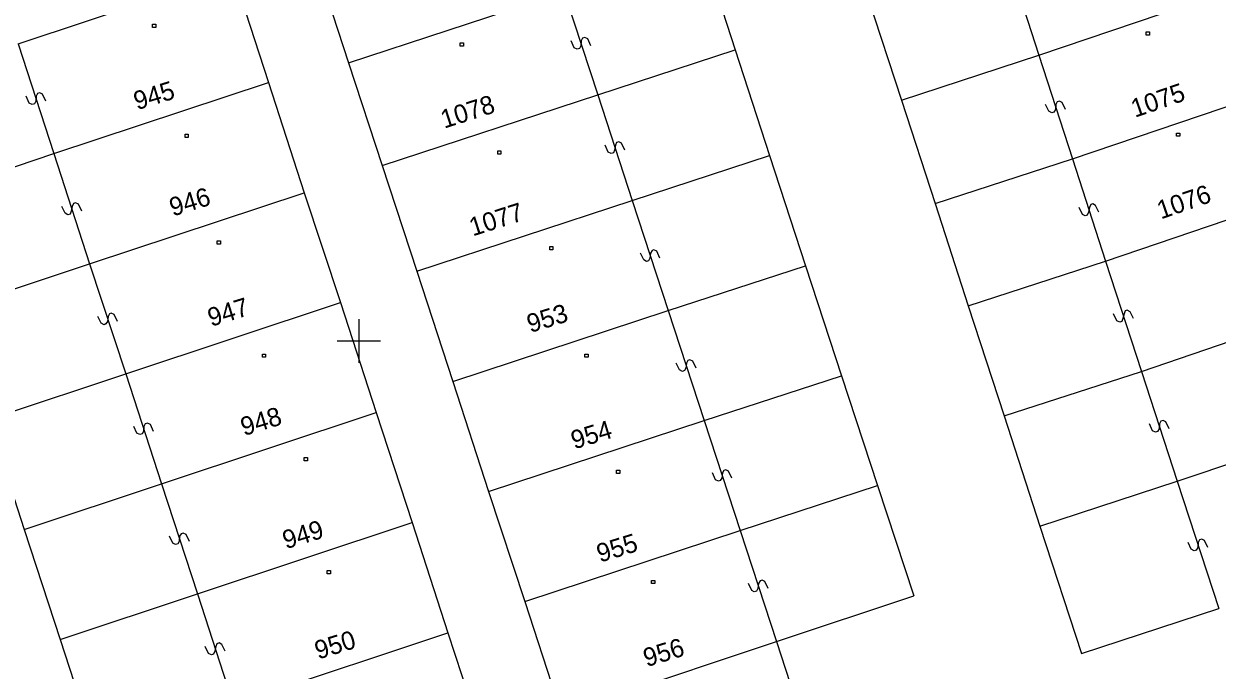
# Model space of a CAD drawing. Extents: x -493352 to -492964, y -1127001 to -1126712.
# Drawn here: x -493269.27 to -493236.25, y -1126749.1 to -1126731.23 of the extents above; entities that cross this region are included whole.
import ezdxf

# ---------------------------------------------------------------- set-up
doc = ezdxf.new("R2010")
doc.units = 0
doc.layers.add('katastrální mapa', color=7, linetype='Continuous')
doc.layers.add('síť', color=7, linetype='Continuous')

msp = doc.modelspace()

# ---------------------------------------------------------------- linework, layer by layer
at = {"layer": 'katastrální mapa'}
for p, q in [((-493250.52, -1126729.1), (-493249.59, -1126731.95)), ((-493242.11, -1126729.25), (-493241.19, -1126732.1)), ((-493261.22, -1126729.46), (-493260.29, -1126732.31)), ((-493269.43, -1126731.78), (-493263.49, -1126729.81)), ((-493263.49, -1126729.81), (-493262.5, -1126732.85)), ((-493241.19, -1126732.1), (-493235.35, -1126730.12)), ((-493260.29, -1126732.31), (-493254.32, -1126730.35)), ((-493254.32, -1126730.35), (-493253.39, -1126733.19)), ((-493245.92, -1126730.49), (-493244.99, -1126733.34)), ((-493265.71, -1126731.24), (-493265.62, -1126731.24)), ((-493265.71, -1126731.33), (-493265.71, -1126731.24)), ((-493265.62, -1126731.33), (-493265.71, -1126731.33)), ((-493265.62, -1126731.24), (-493265.62, -1126731.33)), ((-493238.22, -1126731.45), (-493238.13, -1126731.45)), ((-493238.22, -1126731.54), (-493238.22, -1126731.45)), ((-493238.13, -1126731.54), (-493238.22, -1126731.54)), ((-493238.13, -1126731.45), (-493238.13, -1126731.54)), ((-493269.43, -1126731.78), (-493268.44, -1126734.82)), ((-493257.2, -1126731.76), (-493257.11, -1126731.76)), ((-493257.2, -1126731.85), (-493257.2, -1126731.76)), ((-493257.11, -1126731.85), (-493257.2, -1126731.85)), ((-493257.11, -1126731.76), (-493257.11, -1126731.85)), ((-493254.04, -1126731.89), (-493254.13, -1126731.7)), ((-493253.96, -1126731.93), (-493254.04, -1126731.89)), ((-493253.86, -1126731.84), (-493253.9, -1126731.91)), ((-493253.85, -1126731.7), (-493253.86, -1126731.84)), ((-493253.81, -1126731.63), (-493253.85, -1126731.7)), ((-493253.75, -1126731.61), (-493253.81, -1126731.63)), ((-493253.67, -1126731.65), (-493253.75, -1126731.61)), ((-493253.58, -1126731.84), (-493253.67, -1126731.65)), ((-493253.9, -1126731.91), (-493253.96, -1126731.93)), ((-493253.39, -1126733.19), (-493249.59, -1126731.95)), ((-493249.59, -1126731.95), (-493248.64, -1126734.87)), ((-493244.99, -1126733.34), (-493241.19, -1126732.1)), ((-493241.19, -1126732.1), (-493240.26, -1126734.96)), ((-493260.29, -1126732.31), (-493259.36, -1126735.15)), ((-493268.44, -1126734.82), (-493262.5, -1126732.85)), ((-493262.5, -1126732.85), (-493261.51, -1126735.9)), ((-493268.89, -1126733.16), (-493268.93, -1126733.23)), ((-493268.83, -1126733.14), (-493268.89, -1126733.16)), ((-493268.75, -1126733.18), (-493268.83, -1126733.14)), ((-493268.66, -1126733.37), (-493268.75, -1126733.18)), ((-493259.36, -1126735.15), (-493253.39, -1126733.19)), ((-493253.39, -1126733.19), (-493252.44, -1126736.12)), ((-493240.26, -1126734.96), (-493234.43, -1126732.99)), ((-493269.12, -1126733.42), (-493269.21, -1126733.23)), ((-493269.04, -1126733.46), (-493269.12, -1126733.42)), ((-493268.98, -1126733.44), (-493269.04, -1126733.46)), ((-493268.94, -1126733.37), (-493268.98, -1126733.44)), ((-493268.93, -1126733.23), (-493268.94, -1126733.37)), ((-493244.99, -1126733.34), (-493244.06, -1126736.2)), ((-493240.91, -1126733.65), (-493241, -1126733.46)), ((-493240.72, -1126733.46), (-493240.73, -1126733.6)), ((-493240.68, -1126733.39), (-493240.72, -1126733.46)), ((-493240.62, -1126733.37), (-493240.68, -1126733.39)), ((-493240.54, -1126733.41), (-493240.62, -1126733.37)), ((-493240.45, -1126733.6), (-493240.54, -1126733.41)), ((-493240.83, -1126733.69), (-493240.91, -1126733.65)), ((-493240.77, -1126733.67), (-493240.83, -1126733.69)), ((-493240.73, -1126733.6), (-493240.77, -1126733.67)), ((-493264.81, -1126734.28), (-493264.72, -1126734.28)), ((-493264.81, -1126734.37), (-493264.81, -1126734.28)), ((-493264.72, -1126734.37), (-493264.81, -1126734.37)), ((-493264.72, -1126734.28), (-493264.72, -1126734.37)), ((-493252.87, -1126734.51), (-493252.9, -1126734.59)), ((-493252.81, -1126734.49), (-493252.87, -1126734.51)), ((-493252.73, -1126734.53), (-493252.81, -1126734.49)), ((-493252.64, -1126734.72), (-493252.73, -1126734.53)), ((-493237.38, -1126734.25), (-493237.29, -1126734.25)), ((-493237.38, -1126734.34), (-493237.38, -1126734.25)), ((-493237.29, -1126734.34), (-493237.38, -1126734.34)), ((-493237.29, -1126734.25), (-493237.29, -1126734.34)), ((-493272.23, -1126736.08), (-493268.44, -1126734.82)), ((-493268.44, -1126734.82), (-493267.45, -1126737.87)), ((-493256.16, -1126734.74), (-493256.07, -1126734.74)), ((-493256.16, -1126734.83), (-493256.16, -1126734.74)), ((-493256.07, -1126734.83), (-493256.16, -1126734.83)), ((-493256.07, -1126734.74), (-493256.07, -1126734.83)), ((-493253.1, -1126734.78), (-493253.19, -1126734.59)), ((-493253.02, -1126734.82), (-493253.1, -1126734.78)), ((-493252.96, -1126734.8), (-493253.02, -1126734.82)), ((-493252.93, -1126734.72), (-493252.96, -1126734.8)), ((-493252.9, -1126734.59), (-493252.93, -1126734.72)), ((-493252.44, -1126736.12), (-493248.64, -1126734.87)), ((-493248.64, -1126734.87), (-493247.64, -1126737.92)), ((-493259.36, -1126735.15), (-493258.4, -1126738.07)), ((-493244.06, -1126736.2), (-493240.26, -1126734.96)), ((-493240.26, -1126734.96), (-493239.34, -1126737.79)), ((-493239.34, -1126737.79), (-493233.52, -1126735.82)), ((-493267.84, -1126736.18), (-493267.9, -1126736.2)), ((-493267.76, -1126736.22), (-493267.84, -1126736.18)), ((-493267.45, -1126737.87), (-493261.51, -1126735.9)), ((-493261.51, -1126735.9), (-493260.51, -1126738.94)), ((-493258.4, -1126738.07), (-493252.44, -1126736.12)), ((-493252.44, -1126736.12), (-493251.44, -1126739.16)), ((-493268.13, -1126736.47), (-493268.22, -1126736.28)), ((-493268.05, -1126736.51), (-493268.13, -1126736.47)), ((-493267.99, -1126736.49), (-493268.05, -1126736.51)), ((-493267.96, -1126736.41), (-493267.99, -1126736.49)), ((-493267.93, -1126736.28), (-493267.96, -1126736.41)), ((-493267.9, -1126736.2), (-493267.93, -1126736.28)), ((-493267.67, -1126736.41), (-493267.76, -1126736.22)), ((-493244.06, -1126736.2), (-493243.14, -1126739.03)), ((-493239.98, -1126736.5), (-493240.07, -1126736.31)), ((-493239.91, -1126736.54), (-493239.98, -1126736.5)), ((-493239.85, -1126736.52), (-493239.91, -1126736.54)), ((-493239.81, -1126736.44), (-493239.85, -1126736.52)), ((-493239.79, -1126736.31), (-493239.81, -1126736.44)), ((-493239.75, -1126736.23), (-493239.79, -1126736.31)), ((-493239.69, -1126736.21), (-493239.75, -1126736.23)), ((-493239.62, -1126736.25), (-493239.69, -1126736.21)), ((-493239.53, -1126736.44), (-493239.62, -1126736.25)), ((-493263.92, -1126737.23), (-493263.83, -1126737.23)), ((-493263.92, -1126737.32), (-493263.92, -1126737.23)), ((-493263.83, -1126737.32), (-493263.92, -1126737.32)), ((-493263.83, -1126737.23), (-493263.83, -1126737.32)), ((-493254.72, -1126737.39), (-493254.63, -1126737.39)), ((-493254.72, -1126737.48), (-493254.72, -1126737.39)), ((-493254.63, -1126737.48), (-493254.72, -1126737.48)), ((-493254.63, -1126737.39), (-493254.63, -1126737.48)), ((-493251.89, -1126737.5), (-493251.93, -1126737.57)), ((-493251.84, -1126737.48), (-493251.89, -1126737.5)), ((-493251.76, -1126737.52), (-493251.84, -1126737.48)), ((-493252.12, -1126737.76), (-493252.21, -1126737.57)), ((-493252.04, -1126737.8), (-493252.12, -1126737.76)), ((-493251.99, -1126737.78), (-493252.04, -1126737.8)), ((-493251.95, -1126737.71), (-493251.99, -1126737.78)), ((-493251.93, -1126737.57), (-493251.95, -1126737.71)), ((-493251.67, -1126737.71), (-493251.76, -1126737.52)), ((-493243.14, -1126739.03), (-493239.34, -1126737.79)), ((-493239.34, -1126737.79), (-493238.35, -1126740.84)), ((-493271.24, -1126739.13), (-493267.45, -1126737.87)), ((-493267.45, -1126737.87), (-493266.45, -1126740.91)), ((-493258.4, -1126738.07), (-493257.4, -1126741.12)), ((-493251.44, -1126739.16), (-493247.64, -1126737.92)), ((-493247.64, -1126737.92), (-493246.65, -1126740.96)), ((-493266.45, -1126740.91), (-493260.51, -1126738.94)), ((-493260.51, -1126738.94), (-493259.52, -1126741.98)), ((-493257.4, -1126741.12), (-493251.44, -1126739.16)), ((-493251.44, -1126739.16), (-493250.45, -1126742.2)), ((-493243.14, -1126739.03), (-493242.15, -1126742.07)), ((-493238.74, -1126739.15), (-493238.8, -1126739.17)), ((-493238.66, -1126739.19), (-493238.74, -1126739.15)), ((-493238.35, -1126740.84), (-493232.54, -1126738.87)), ((-493267.13, -1126739.51), (-493267.22, -1126739.32)), ((-493266.96, -1126739.46), (-493267, -1126739.53)), ((-493266.94, -1126739.32), (-493266.96, -1126739.46)), ((-493266.9, -1126739.25), (-493266.94, -1126739.32)), ((-493266.85, -1126739.23), (-493266.9, -1126739.25)), ((-493266.77, -1126739.27), (-493266.85, -1126739.23)), ((-493266.68, -1126739.46), (-493266.77, -1126739.27)), ((-493239.03, -1126739.44), (-493239.12, -1126739.25)), ((-493238.95, -1126739.48), (-493239.03, -1126739.44)), ((-493238.89, -1126739.46), (-493238.95, -1126739.48)), ((-493238.86, -1126739.38), (-493238.89, -1126739.46)), ((-493238.83, -1126739.25), (-493238.86, -1126739.38)), ((-493238.8, -1126739.17), (-493238.83, -1126739.25)), ((-493238.57, -1126739.38), (-493238.66, -1126739.19)), ((-493267.05, -1126739.55), (-493267.13, -1126739.51)), ((-493267, -1126739.53), (-493267.05, -1126739.55)), ((-493262.67, -1126740.36), (-493262.58, -1126740.36)), ((-493262.67, -1126740.45), (-493262.67, -1126740.36)), ((-493262.58, -1126740.45), (-493262.67, -1126740.45)), ((-493262.58, -1126740.36), (-493262.58, -1126740.45)), ((-493253.75, -1126740.36), (-493253.66, -1126740.36)), ((-493253.75, -1126740.45), (-493253.75, -1126740.36)), ((-493253.66, -1126740.45), (-493253.75, -1126740.45)), ((-493253.66, -1126740.36), (-493253.66, -1126740.45)), ((-493251.13, -1126740.8), (-493251.22, -1126740.61)), ((-493251.05, -1126740.84), (-493251.13, -1126740.8)), ((-493250.95, -1126740.75), (-493250.99, -1126740.82)), ((-493250.94, -1126740.61), (-493250.95, -1126740.75)), ((-493250.9, -1126740.54), (-493250.94, -1126740.61)), ((-493250.84, -1126740.52), (-493250.9, -1126740.54)), ((-493250.76, -1126740.56), (-493250.84, -1126740.52)), ((-493250.67, -1126740.75), (-493250.76, -1126740.56)), ((-493270.25, -1126742.17), (-493266.45, -1126740.91)), ((-493266.45, -1126740.91), (-493265.46, -1126743.95)), ((-493257.4, -1126741.12), (-493256.41, -1126744.16)), ((-493250.99, -1126740.82), (-493251.05, -1126740.84)), ((-493250.45, -1126742.2), (-493246.65, -1126740.96)), ((-493246.65, -1126740.96), (-493245.65, -1126744)), ((-493242.15, -1126742.07), (-493238.35, -1126740.84)), ((-493238.35, -1126740.84), (-493237.36, -1126743.88)), ((-493265.46, -1126743.95), (-493259.52, -1126741.98)), ((-493259.52, -1126741.98), (-493258.53, -1126745.02)), ((-493242.15, -1126742.07), (-493241.16, -1126745.12)), ((-493237.36, -1126743.88), (-493231.56, -1126741.92)), ((-493270.25, -1126742.17), (-493269.26, -1126745.21)), ((-493266.14, -1126742.55), (-493266.23, -1126742.36)), ((-493265.95, -1126742.36), (-493265.96, -1126742.5)), ((-493265.91, -1126742.29), (-493265.95, -1126742.36)), ((-493265.85, -1126742.27), (-493265.91, -1126742.29)), ((-493265.77, -1126742.31), (-493265.85, -1126742.27)), ((-493265.68, -1126742.5), (-493265.77, -1126742.31)), ((-493256.41, -1126744.16), (-493250.45, -1126742.2)), ((-493250.45, -1126742.2), (-493249.45, -1126745.24)), ((-493238.04, -1126742.48), (-493238.13, -1126742.29)), ((-493237.86, -1126742.43), (-493237.9, -1126742.5)), ((-493237.85, -1126742.29), (-493237.86, -1126742.43)), ((-493237.81, -1126742.22), (-493237.85, -1126742.29)), ((-493237.75, -1126742.2), (-493237.81, -1126742.22)), ((-493237.67, -1126742.24), (-493237.75, -1126742.2)), ((-493237.58, -1126742.43), (-493237.67, -1126742.24)), ((-493266.06, -1126742.59), (-493266.14, -1126742.55)), ((-493266, -1126742.57), (-493266.06, -1126742.59)), ((-493265.96, -1126742.5), (-493266, -1126742.57)), ((-493237.96, -1126742.52), (-493238.04, -1126742.48)), ((-493237.9, -1126742.5), (-493237.96, -1126742.52)), ((-493261.51, -1126743.22), (-493261.42, -1126743.22)), ((-493261.51, -1126743.31), (-493261.51, -1126743.22)), ((-493261.42, -1126743.31), (-493261.51, -1126743.31)), ((-493261.42, -1126743.22), (-493261.42, -1126743.31)), ((-493252.87, -1126743.57), (-493252.78, -1126743.57)), ((-493252.87, -1126743.66), (-493252.87, -1126743.57)), ((-493252.78, -1126743.66), (-493252.87, -1126743.66)), ((-493252.78, -1126743.57), (-493252.78, -1126743.66)), ((-493250.13, -1126743.84), (-493250.22, -1126743.65)), ((-493249.94, -1126743.65), (-493249.96, -1126743.79)), ((-493249.9, -1126743.58), (-493249.94, -1126743.65)), ((-493249.85, -1126743.56), (-493249.9, -1126743.58)), ((-493249.77, -1126743.6), (-493249.85, -1126743.56)), ((-493249.68, -1126743.79), (-493249.77, -1126743.6)), ((-493269.26, -1126745.21), (-493265.46, -1126743.95)), ((-493265.46, -1126743.95), (-493264.47, -1126746.99)), ((-493250.05, -1126743.88), (-493250.13, -1126743.84)), ((-493250, -1126743.86), (-493250.05, -1126743.88)), ((-493249.96, -1126743.79), (-493250, -1126743.86)), ((-493249.45, -1126745.24), (-493245.65, -1126744)), ((-493245.65, -1126744), (-493244.65, -1126747.05)), ((-493241.16, -1126745.12), (-493237.36, -1126743.88)), ((-493237.36, -1126743.88), (-493236.21, -1126747.4)), ((-493256.41, -1126744.16), (-493255.41, -1126747.2)), ((-493264.47, -1126746.99), (-493258.53, -1126745.02)), ((-493258.53, -1126745.02), (-493257.54, -1126748.07)), ((-493269.26, -1126745.21), (-493268.27, -1126748.25)), ((-493265.15, -1126745.59), (-493265.24, -1126745.4)), ((-493264.96, -1126745.4), (-493264.97, -1126745.54)), ((-493264.92, -1126745.33), (-493264.96, -1126745.4)), ((-493264.86, -1126745.31), (-493264.92, -1126745.33)), ((-493264.78, -1126745.35), (-493264.86, -1126745.31)), ((-493264.69, -1126745.54), (-493264.78, -1126745.35)), ((-493255.41, -1126747.2), (-493249.45, -1126745.24)), ((-493249.45, -1126745.24), (-493248.45, -1126748.31)), ((-493241.16, -1126745.12), (-493240.01, -1126748.64)), ((-493265.07, -1126745.63), (-493265.15, -1126745.59)), ((-493265.01, -1126745.61), (-493265.07, -1126745.63)), ((-493264.97, -1126745.54), (-493265.01, -1126745.61)), ((-493236.97, -1126745.76), (-493237.06, -1126745.57)), ((-493236.89, -1126745.8), (-493236.97, -1126745.76)), ((-493236.79, -1126745.71), (-493236.83, -1126745.78)), ((-493236.78, -1126745.57), (-493236.79, -1126745.71)), ((-493236.74, -1126745.5), (-493236.78, -1126745.57)), ((-493236.68, -1126745.48), (-493236.74, -1126745.5)), ((-493236.6, -1126745.52), (-493236.68, -1126745.48)), ((-493236.51, -1126745.71), (-493236.6, -1126745.52)), ((-493236.83, -1126745.78), (-493236.89, -1126745.8)), ((-493260.88, -1126746.35), (-493260.79, -1126746.35)), ((-493260.88, -1126746.44), (-493260.88, -1126746.35)), ((-493260.79, -1126746.35), (-493260.79, -1126746.44)), ((-493260.79, -1126746.44), (-493260.88, -1126746.44)), ((-493251.9, -1126746.62), (-493251.81, -1126746.62)), ((-493251.9, -1126746.71), (-493251.9, -1126746.62)), ((-493251.81, -1126746.71), (-493251.9, -1126746.71)), ((-493251.81, -1126746.62), (-493251.81, -1126746.71)), ((-493249.13, -1126746.9), (-493249.22, -1126746.71)), ((-493248.94, -1126746.71), (-493248.96, -1126746.84)), ((-493248.9, -1126746.63), (-493248.94, -1126746.71)), ((-493248.84, -1126746.61), (-493248.9, -1126746.63)), ((-493248.77, -1126746.65), (-493248.84, -1126746.61)), ((-493248.68, -1126746.84), (-493248.77, -1126746.65)), ((-493268.27, -1126748.25), (-493264.47, -1126746.99)), ((-493264.47, -1126746.99), (-493263.48, -1126750.04)), ((-493249.06, -1126746.94), (-493249.13, -1126746.9)), ((-493249, -1126746.92), (-493249.06, -1126746.94)), ((-493248.96, -1126746.84), (-493249, -1126746.92)), ((-493248.45, -1126748.31), (-493244.65, -1126747.05)), ((-493255.41, -1126747.2), (-493254.4, -1126750.29)), ((-493240.01, -1126748.64), (-493236.21, -1126747.4)), ((-493263.48, -1126750.04), (-493257.54, -1126748.07)), ((-493257.54, -1126748.07), (-493256.57, -1126751.03)), ((-493268.27, -1126748.25), (-493267.27, -1126751.29)), ((-493263.93, -1126748.37), (-493263.96, -1126748.45)), ((-493263.87, -1126748.35), (-493263.93, -1126748.37)), ((-493263.79, -1126748.39), (-493263.87, -1126748.35)), ((-493263.7, -1126748.58), (-493263.79, -1126748.39)), ((-493254.4, -1126750.29), (-493248.45, -1126748.31)), ((-493248.45, -1126748.31), (-493247.36, -1126751.63)), ((-493264.16, -1126748.64), (-493264.25, -1126748.45)), ((-493264.08, -1126748.68), (-493264.16, -1126748.64)), ((-493264.02, -1126748.66), (-493264.08, -1126748.68)), ((-493263.99, -1126748.58), (-493264.02, -1126748.66)), ((-493263.96, -1126748.45), (-493263.99, -1126748.58))]:
    msp.add_line(p, q, dxfattribs=at)
at = {"layer": 'síť'}
for p, q in [((-493260, -1126739.4), (-493260, -1126740.6)), ((-493260.6, -1126740), (-493259.4, -1126740))]:
    msp.add_line(p, q, dxfattribs=at)

# ---------------------------------------------------------------- texts
at = {"layer": 'katastrální mapa'}
for s, rotation, p in [('945', 17.073, (-493266.14, -1126733.62)), ('1075', 19.026, (-493238.53, -1126733.83)), ('1078', 17.703, (-493257.64, -1126734.13)), ('946', 17.073, (-493265.15, -1126736.56)), ('1076', 19.026, (-493237.81, -1126736.64)), ('1077', 17.703, (-493256.85, -1126737.11)), ('947', 17.073, (-493264.09, -1126739.61)), ('953', 17.019, (-493255.26, -1126739.78)), ('948', 17.073, (-493263.18, -1126742.63)), ('954', 17.019, (-493254.04, -1126743)), ('949', 17.073, (-493262.02, -1126745.76)), ('955', 17.019, (-493253.33, -1126746.13)), ('950', 17.073, (-493261.13, -1126748.81)), ('956', 17.019, (-493252.04, -1126749.02))]:
    msp.add_text(s, height=0.51, rotation=rotation, dxfattribs=at).set_placement(p)

doc.saveas('drawing.dxf')
